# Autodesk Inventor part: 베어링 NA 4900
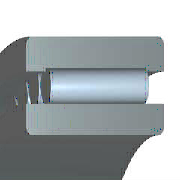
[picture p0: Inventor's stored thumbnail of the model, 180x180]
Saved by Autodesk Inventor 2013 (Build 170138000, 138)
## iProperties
Created: 2009-02
Part Number: 베어링 NA 4900
Material: 스테인리스강
Description: 니들 롤러 베어링 - 경계 치수 및 공차
Document SubType Name: Modeling
Standard: KS B 2029
Designer: SeoGD™
Standards Organization: KS
Language: ko-KR
Size Designation: NA 4900 - 10 x 22 x 13
Categories: <MemberInstance><Categories><Category DisplayName="샤프트 부품" InternalName="7f7aeb1f-a693-4053-b835-cee3144e0d98" Mnemonic="SHFT"><Category DisplayName="베어링" Inter
Density: 1 g/cm^3
IsCustomPart: 0
Author: SeoGD™
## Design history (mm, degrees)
sketch "스케치"
  geometry: L1 (1.857, 9)-(11.143, 9); L2 (11.143, 9)-(11.143, 7); L3 (13, 7)-(0, 7); L4 (1.857, 7)-(1.857, 9); L5 (1.857, 8)-(11.143, 8); L6 (6.5, 8)-(6.5, 7); L7 (0, 5)-(13, 5); L8 (0, 11)-(13, 11); L9 (13, 5)-(13, 7); L10 (13, 8.8)-(13, 11); L11 (1.857, 8.8)-(0, 8.8); L12 (11.143, 8.8)-(13, 8.8); L13 (-6, 0)-(36, 0) reference; L14 (0, -1.9)-(0, 14.9) reference
  constraints: 24 end point, 8 point on line, 3 midpoint, 3 parallel, 3 perpendicular, 2 symmetric about line, 1 horizontal, 1 other
  dimensions: "d6" = 10 diameter of L7 L13 (= WD); "d7" = 14 diameter of L3 L13 (= KID1); "d8" = 22 diameter of L8 L13 (= BD); "d9" = 16 diameter of L6.start L13 (= 0.5 x WD + 0.5 x BD); "d10" = 17.6 diameter of L12 L13 (= 0.9 x BD + 0.9 x WD - 0.8 x KID1); "d11" = 18 diameter of L1 L13 (= BD + WD - KID1); "d12" = 1.85714 distance between parallel lines of L14 L4 (= 0.142857 x KB); "d13" = 13 distance between parallel lines of L14 L9 (= KB); "d14" = 11.14286 distance between parallel lines of L14 L2 (= 0.857143 x KB)
revolve "본체" stored, may be unused: angle "d17" = 90 deg
revolve "롤러" stored, may be unused: angle "d18" = 90 deg
pattern_circular "IDS_ARRAYROLLER[SIMPL:T]" dims angle "d2" = 360 deg
body "Solid1"
fillet "모깎기1" dims "d0" = 0.3 (= KRS)
other parameters: "WD" = 10 [user parameter; used in 6 equation terms], "BD" = 22 [user parameter; used in 6 equation terms], "KB" = 13 [user parameter; used in 3 equation terms], "KID1" = 14 [user parameter; used in 4 equation terms], "KRS" = 0.3 [user parameter; used in 1 equation term], "d3" = 0, "d4" = 0, "d5" = 0, "d15" = 0, "d16" = 0, "BC0" = 9150000 [user parameter], "WR" = 5 (= 0.5 x WD) [user parameter], "BBA" = 0 [user parameter], "BC" = 8150000 [user parameter], "BR" = 11 (= 0.5 x BD) [user parameter]
